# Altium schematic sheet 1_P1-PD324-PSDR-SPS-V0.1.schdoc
size 848 x 601 mm; Symbol: Drawing-Symbol_A4; Device: Drawing-Symbol_A4; Company: 嘉立创EDA; Version: V1.0; Page Size: A4; @Project Name: PD324; @Page Count: 2; @Update Date: 2025-04-30; @Create Date: 2025-04-12; @Schematic Name: Schematic1; @Page No: 1; @Page Name: P1-PD324-PSDR-SPS-V0.1; @Create Time: 09:33:54; @Update Time: 09:23:29; Width: 3304; Height: 2338; Region Start: 1; X Region Count: 6; Y Region Count: 4; Blade Width: 10; Title Block Position: 3; @Board Name: Board1
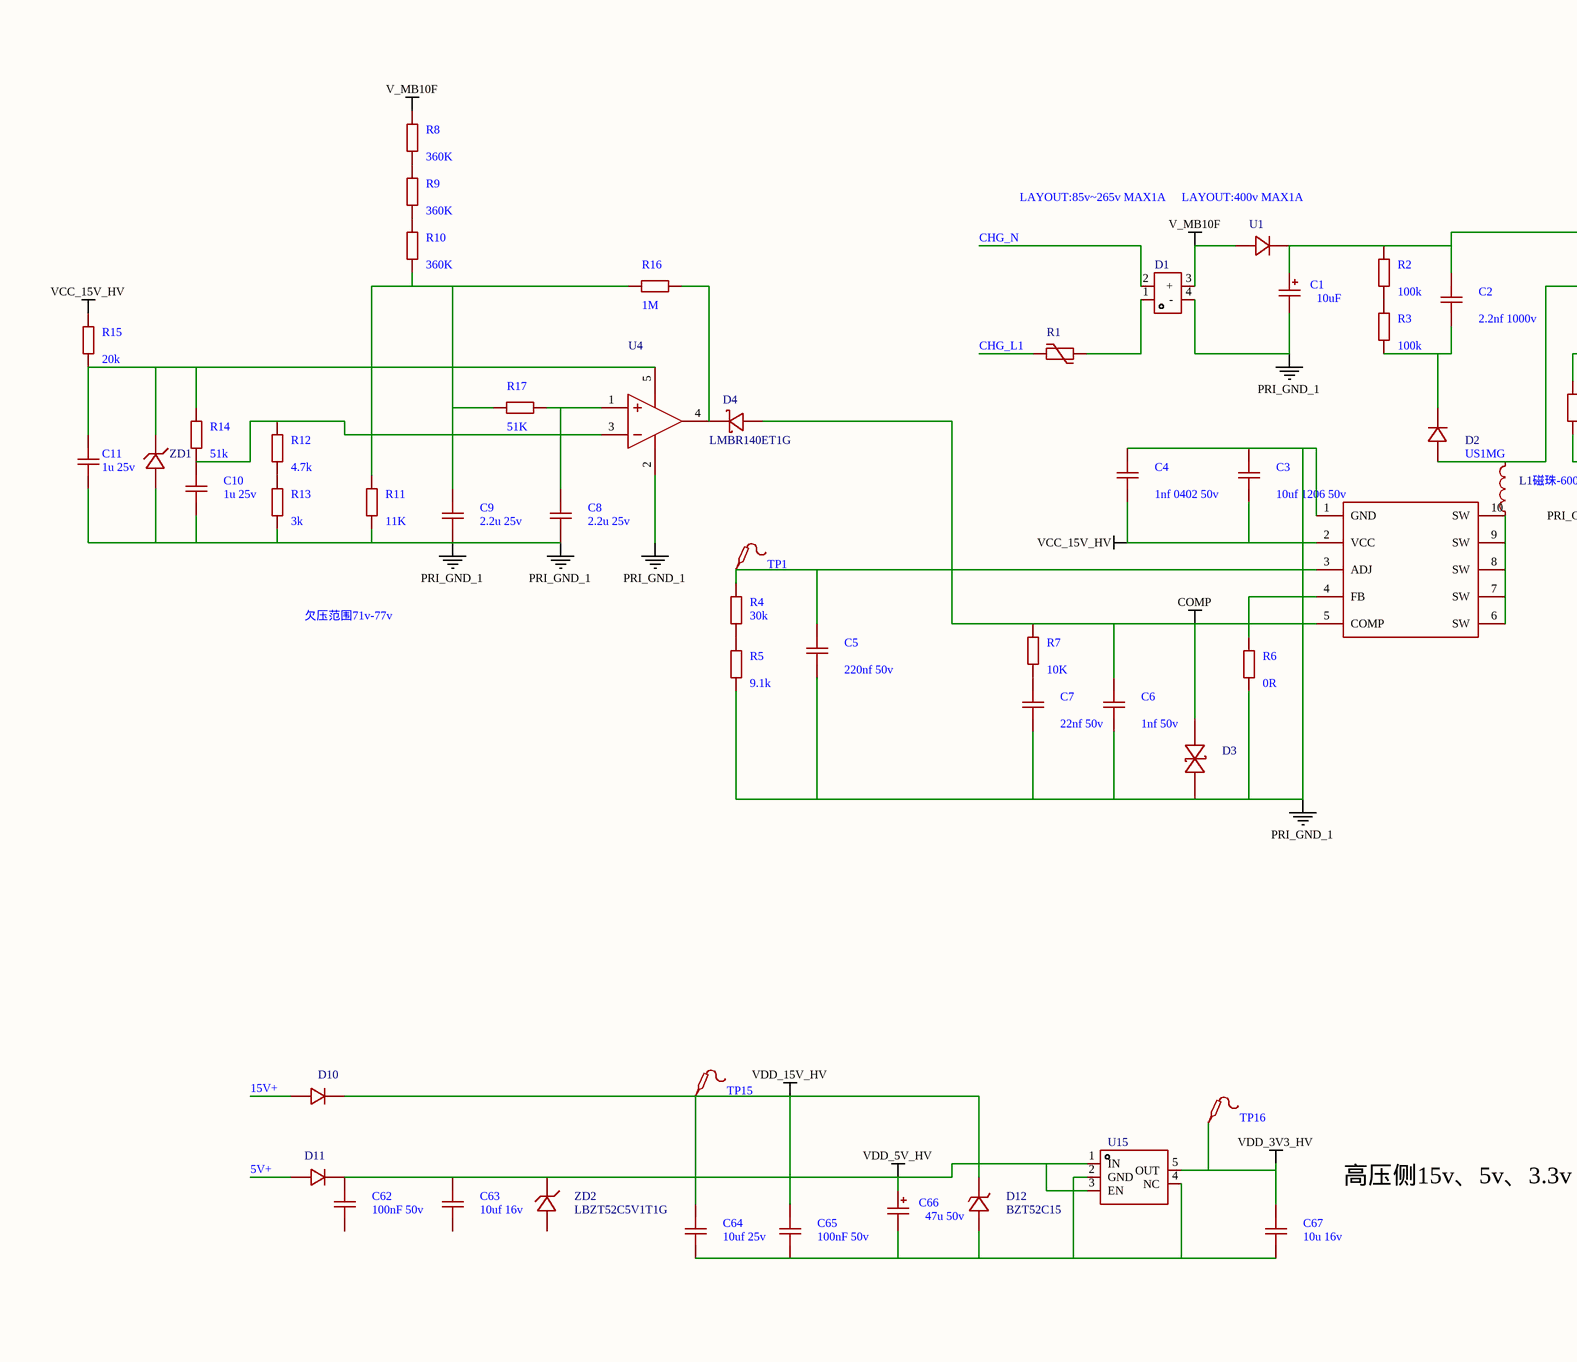
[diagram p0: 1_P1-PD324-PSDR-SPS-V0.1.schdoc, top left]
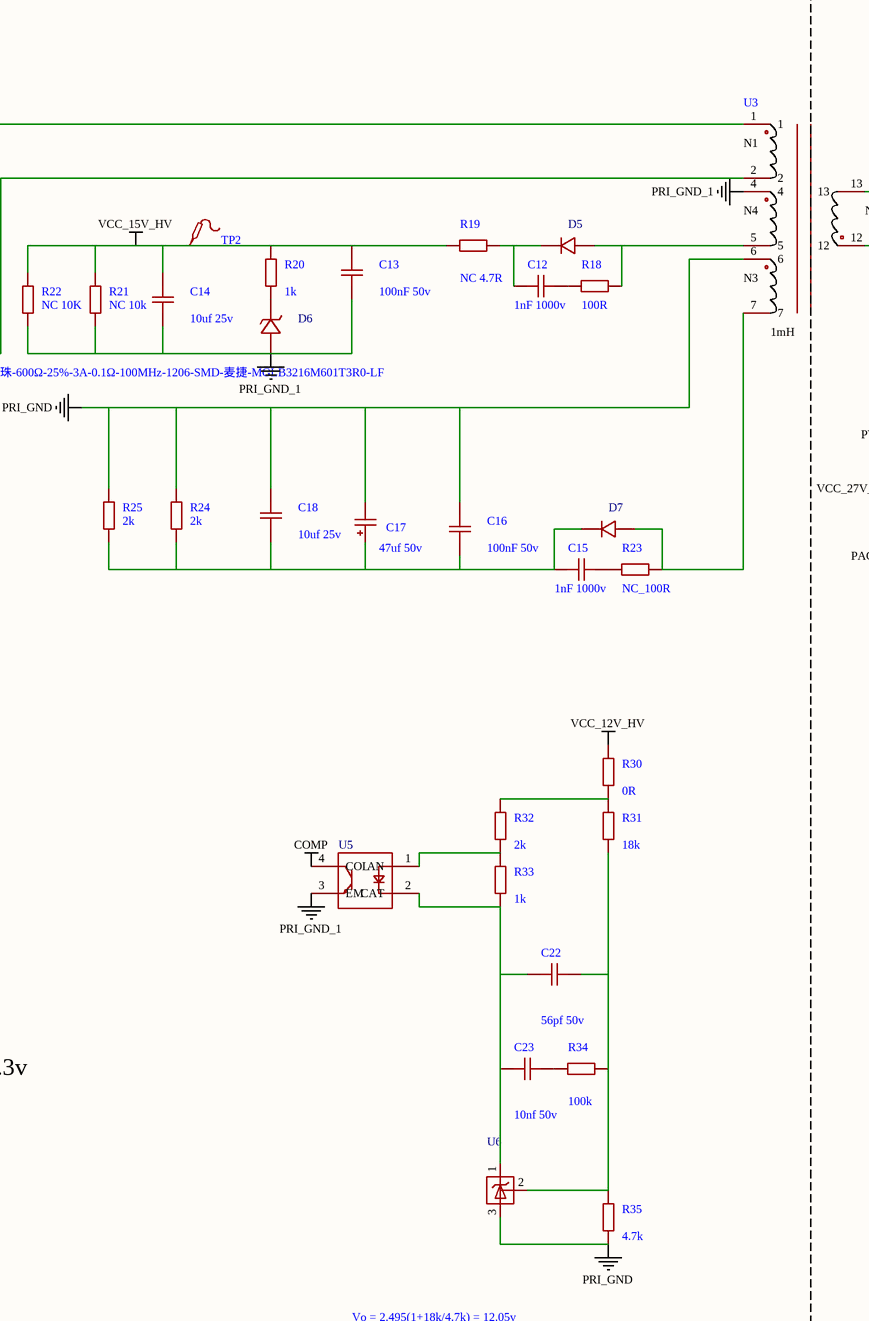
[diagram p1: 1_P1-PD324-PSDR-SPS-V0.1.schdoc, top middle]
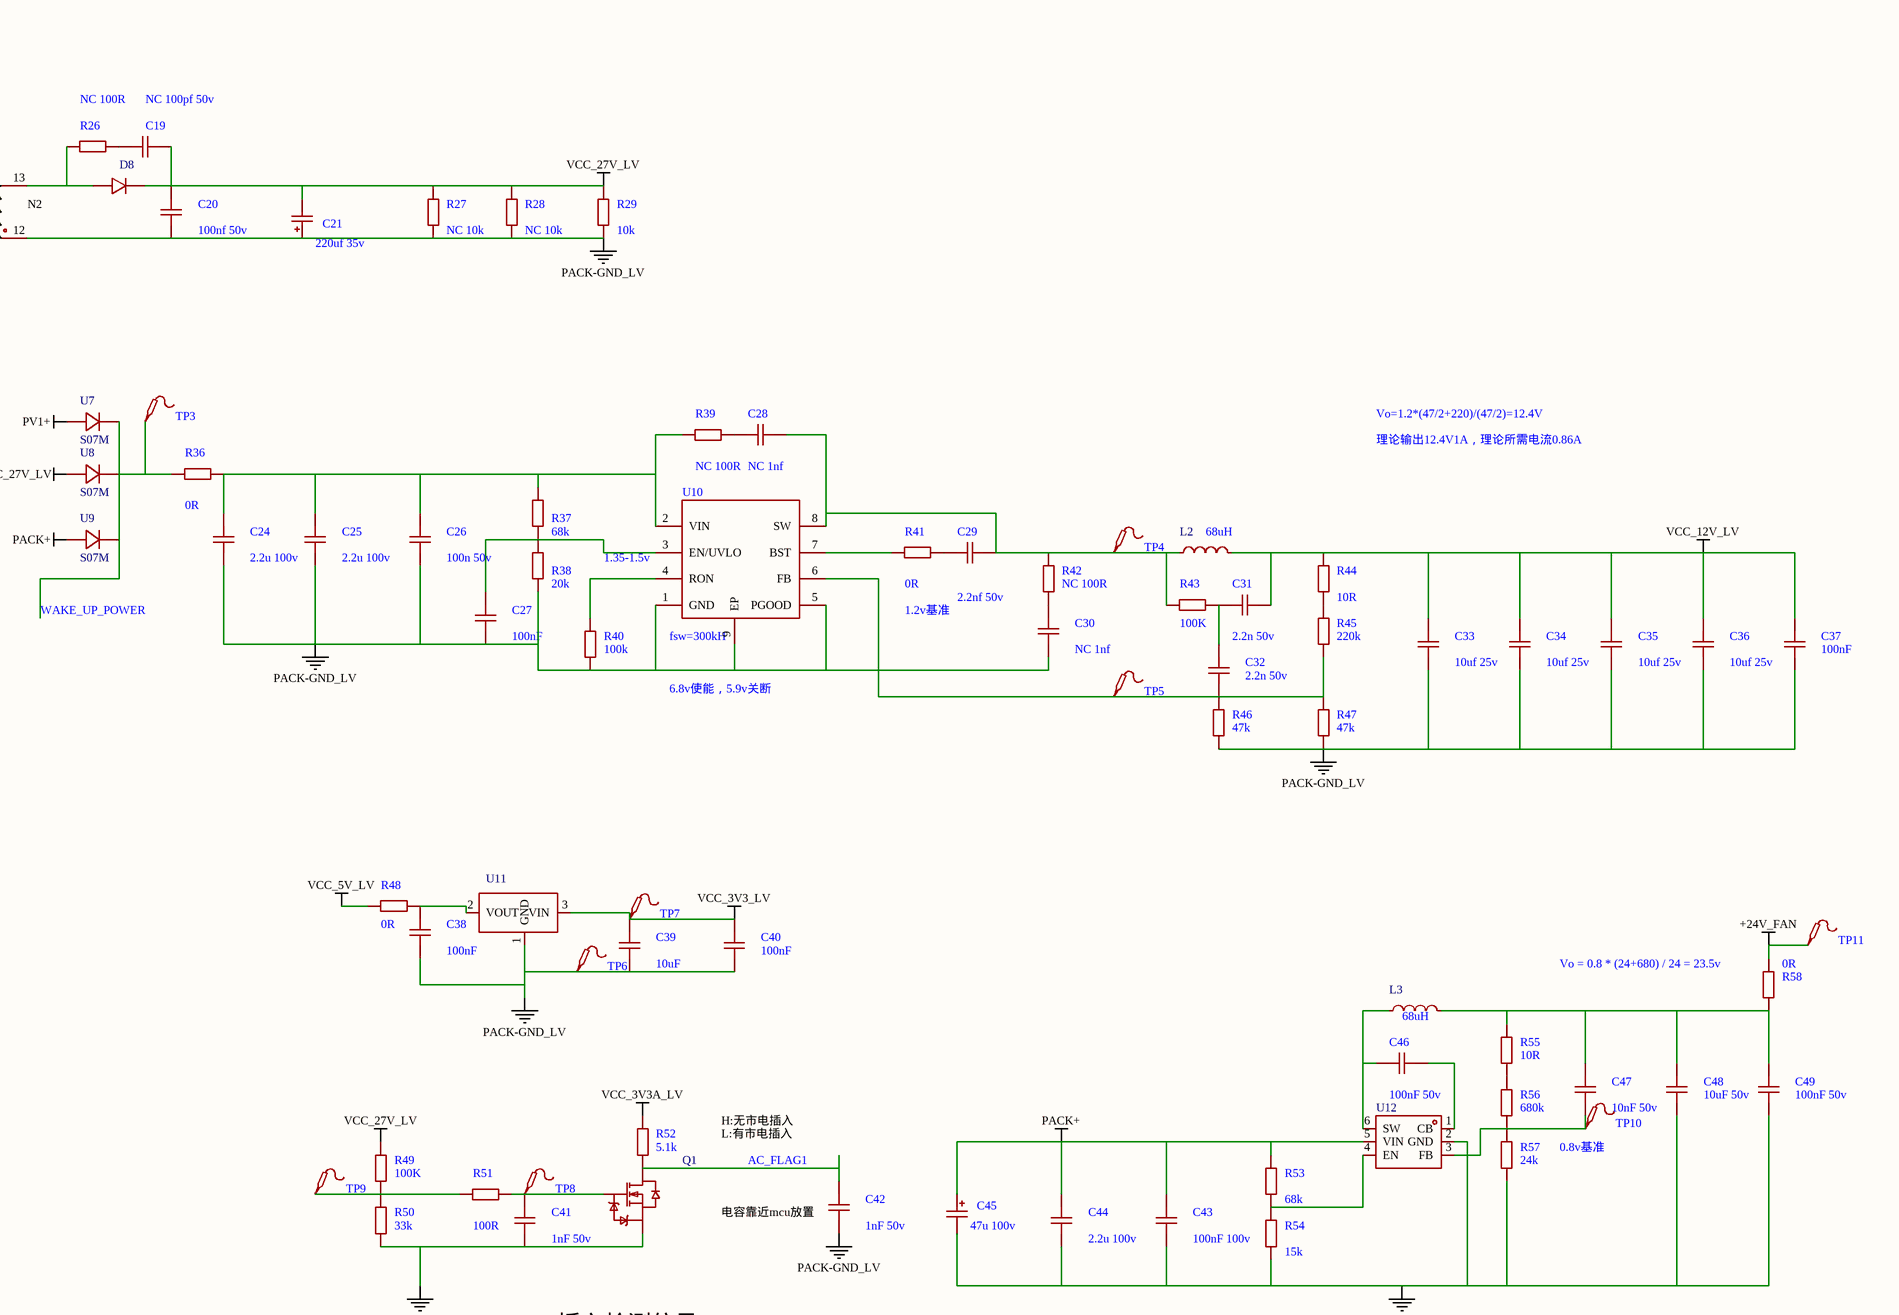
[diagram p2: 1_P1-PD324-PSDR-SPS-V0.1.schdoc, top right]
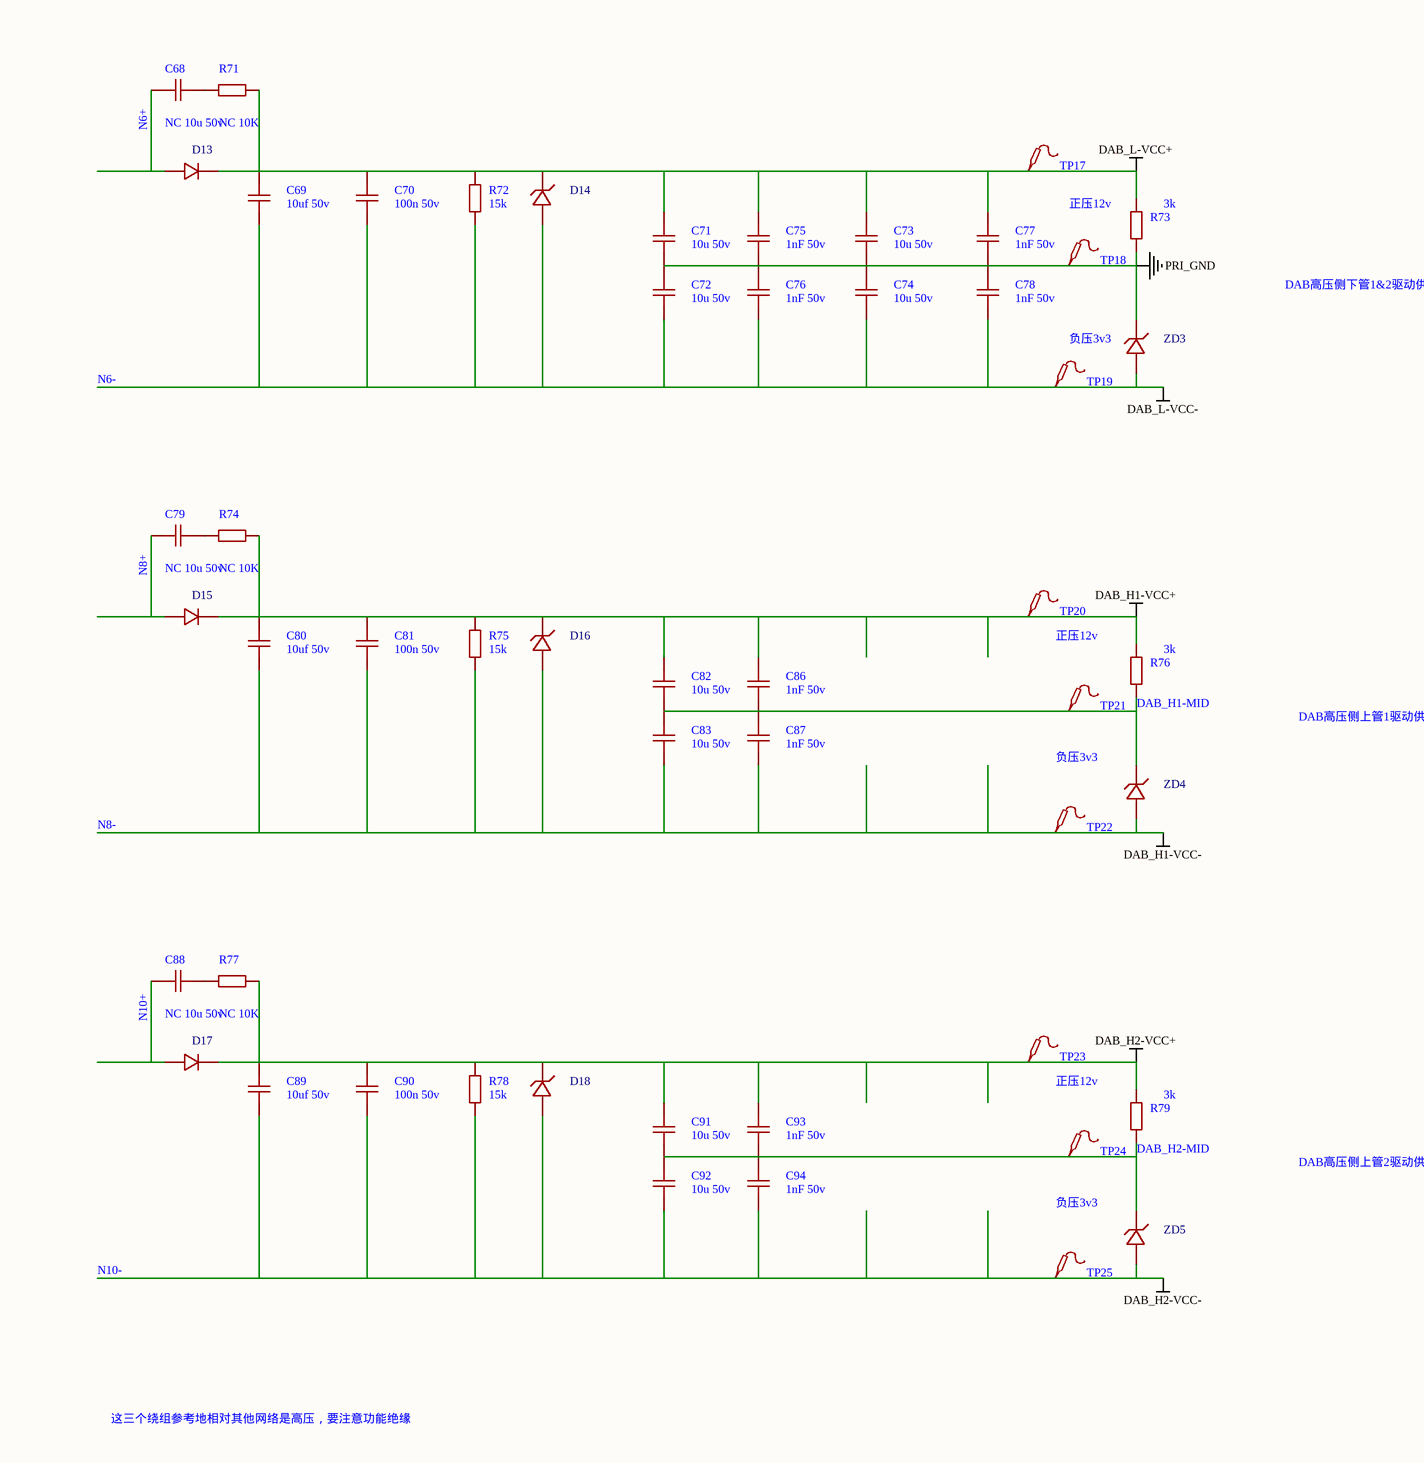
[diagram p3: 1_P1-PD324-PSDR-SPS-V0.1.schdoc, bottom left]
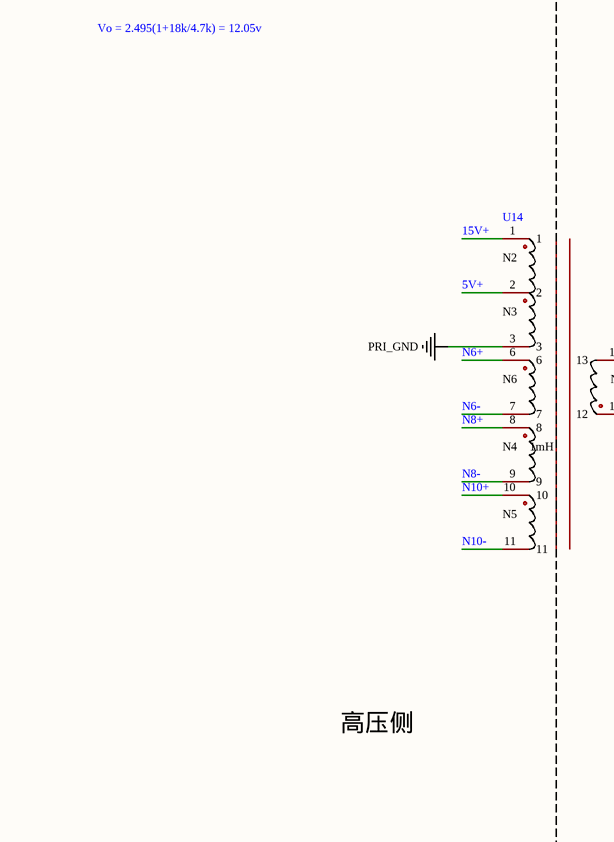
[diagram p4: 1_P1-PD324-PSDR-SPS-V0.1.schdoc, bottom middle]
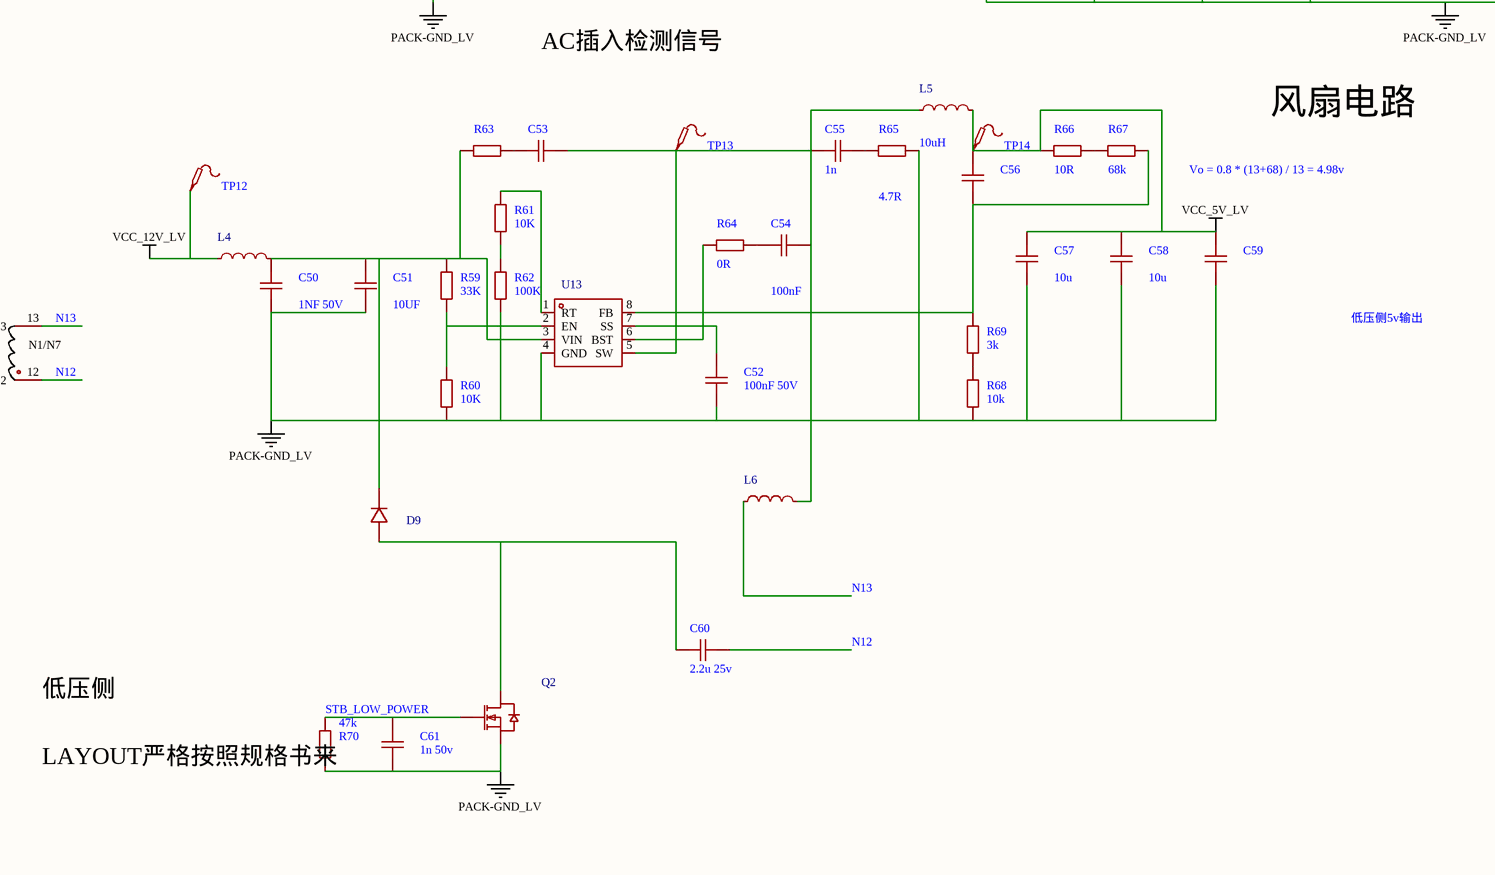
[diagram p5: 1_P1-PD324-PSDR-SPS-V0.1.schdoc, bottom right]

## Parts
C1  10uF  [C_Ele_SMD_3x5.4mm]
C2  2.2nf 1000v  [C1206]
C3  10uf 1206 50v  [C1206]
C4  1nf 0402 50v  [C1206]
C5  220nf 50v  [C0603]
C6  1nf 50v  [C0402]
C7  22nf 50v  [C0603]
C8  2.2u 25v  [C0805]
C9  2.2u 25v  [C0805]
C10  1u 25v  [C0805]
C11  1u 25v  [C0805]
C12  1nF 1000v  [C1206]
C13  100nF 50v  [C0603]
C14  10uf 25v  [C1206]
C15  1nF 1000v  [C1206]
C16  100nF 50v  [C0603]
C17  47uf 50v  [C_Ele_SMD_3x5.4mm]
C18  10uf 25v  [C1206]
C19  NC 100pf 50v  [C0603]
C20  100nf 50v  [C0603]
C21  220uf 35v  [C_Ele_SMD_3x5.4mm]
C22  56pf 50v  [C0402]
C23  10nf 50v  [C0402]
C24  2.2u 100v  [C1206]
C25  2.2u 100v  [C1206]
C26  100n 50v  [C1206]
C27  100nF  [C0603]
C28  NC 1nf  [C1206]
C29  2.2nf 50v  [C0402]
C30  NC 1nf  [C0402]
C31  2.2n 50v  [C0402]
C32  2.2n 50v  [C0402]
C33  10uf 25v  [C1206]
C34  10uf 25v  [C1206]
C35  10uf 25v  [C1206]
C36  10uf 25v  [C1206]
C37  100nF  [C0603]
C38  100nF  [C0603]
C39  10uF  [C0603]
C40  100nF  [C0402]
C41  1nF 50v  [C0402]
C42  1nF 50v  [C0402]
C43  100nF 100v  [C1206]
C44  2.2u 100v  [C1206]
C45  47u 100v  [C_Ele_SMD_3x5.4mm]
C46  100nF 50v  [C0603]
C47  10nF 50v  [C0402]
C48  10uF 50v  [C1206]
C49  100nF 50v  [C0603]
C50  1NF 50V  [C0402]
C51  10UF  [C1206]
C52  100nF 50V  [C0603]
C53  1nF 50V  [C0402]  (value not drawn)
C54  100nF  [C0603]
C55  1n  [C0402]
C56  NC 12p  [C0402]  (value not drawn)
C57  10u  [C1206]
C58  10u  [C1206]
C59  100nF  [C0402]  (value not drawn)
C60  2.2u 25v  [C0805]
C61  1n 50v  [C0402]
C62  100nF 50v  [C0603]
C63  10uf 16v  [C0805]
C64  10uf 25v  [C1206]
C65  100nF 50v  [C0603]
C66  47u 50v  [C_Ele_SMD_3x5.4mm]
C67  10u 16v  [C0805]
C68  NC 10u 50v  [C1206]
C69  10uf 50v  [C1206]
C70  100n 50v  [C0603]
C71  10u 50v  [C1206]
C72  10u 50v  [C1206]
C73  10u 50v  [C1206]
C74  10u 50v  [C1206]
C75  1nF 50v  [C0603]
C76  1nF 50v  [C0603]
C77  1nF 50v  [C0603]
C78  1nF 50v  [C0603]
C79  NC 10u 50v  [C1206]
C80  10uf 50v  [C1206]
C81  100n 50v  [C0603]
C82  10u 50v  [C1206]
C83  10u 50v  [C1206]
C86  1nF 50v  [C0603]
C87  1nF 50v  [C0603]
C88  NC 10u 50v  [C1206]
C89  10uf 50v  [C1206]
C90  100n 50v  [C0603]
C91  10u 50v  [C1206]
C92  10u 50v  [C1206]
C93  1nF 50v  [C0603]
C94  1nF 50v  [C0603]
D1  MB10F  [MBF_L4.8-W3.9-P2.50-LS6.7-TL]  (value not drawn)
D2  US1MG  [SMA_L4.3-W2.6-LS5.2-RD]
D3  SMAJ36CA  [SMA_L4.4-W2.8-LS5.1-BI]  (value not drawn)
D4  LMBR140ET1G  [SOD-323HE_L2.0-W1.4-LS2.5-RD]
D5  SODSF14-SH  [SOD-123FL_L2.8-W1.8-LS3.7-RD-1]  (value not drawn)
D6  BZT52C15  [SOD-123_L2.7-W1.7-LS3.8-RD]  (value not drawn)
D7  SODSF14-SH  [SOD-123FL_L2.8-W1.8-LS3.7-RD-1]  (value not drawn)
D8  SODSF14-SH  [SOD-123FL_L2.8-W1.8-LS3.7-RD-1]  (value not drawn)
D9  SODSF14-SH  [SOD-123FL_L2.8-W1.8-LS3.7-RD-1]  (value not drawn)
D10  ES07D  [SOD-123FL_L2.7-W1.8-LS3.8-RD]  (value not drawn)
D11  ES07D  [SOD-123FL_L2.7-W1.8-LS3.8-RD]  (value not drawn)
D12  BZT52C15  [SOD-123_L2.7-W1.7-LS3.8-RD]
D13  ES07D  [SOD-123FL_L2.7-W1.8-LS3.8-RD]  (value not drawn)
D14  LM3Z18VT1G  [SOD-323_L1.8-W1.3-LS2.5-RD]  (value not drawn)
D15  ES07D  [SOD-123FL_L2.7-W1.8-LS3.8-RD]  (value not drawn)
D16  LM3Z18VT1G  [SOD-323_L1.8-W1.3-LS2.5-RD]  (value not drawn)
D17  ES07D  [SOD-123FL_L2.7-W1.8-LS3.8-RD]  (value not drawn)
D18  LM3Z18VT1G  [SOD-323_L1.8-W1.3-LS2.5-RD]  (value not drawn)
L1  磁珠-600Ω-25%-3A-0.1Ω-100MHz-1206-SMD-麦捷-MGLB3216M601T3R0-LF  [L1206]
L2  68uH  [L0603]
L3  68uH  [L0603]
L4  磁珠-600Ω-25%-3A-0.1Ω-100MHz-1206-SMD-麦捷-MGLB3216M601T3R0-LF  [L1206]  (value not drawn)
L5  10uH  [L1206]
L6  磁珠-100MHz-120Ω-25%-3A-0.06Ω-SMD-麦捷-MGLB1608M121T3R0-LF  [L0603]  (value not drawn)
Q1  L2N7002SLT1G  [SOT-23_L2.9-W1.3-P1.90-LS2.4-BR]  (value not drawn)
Q2  YJL3400A  [SOT-23-3_L2.9-W1.3-P1.90-LS2.4-BR]  (value not drawn)
R1  MF0903003M4BP0FPT0  [RES-TH_L11.0-W6.0-P5.00-D0.7-S6.40]  (value not drawn)
R2  100k  [R1206]
R3  100k  [R1206]
R4  30k  [R0603]
R5  9.1k  [R0603]
R6  0R  [R0603]
R7  10K  [R0603]
R8  360K  [R1206]
R9  360K  [R1206]
R10  360K  [R1206]
R11  11K  [R0603]
R12  4.7k  [R0603]
R13  3k  [R0603]
R14  51k  [R0603]
R15  20k  [R0603]
R16  1M  [R0603]
R17  51K  [R0603]
R18  100R  [R1206]
R19  NC 4.7R  [R1206]
R20  1k  [R0603]
R21  NC 10k  [R1206]
R22  NC 10K  [R1206]
R23  NC_100R  [R1206]
R24  2k  [R1206]
R25  2k  [R1206]
R26  NC 100R  [R1206]
R27  NC 10k  [R1206]
R28  NC 10k  [R1206]
R29  10k  [R1206]
R30  0R  [R0603]
R31  18k  [R0603]
R32  2k  [R0603]
R33  1k  [R0603]
R34  100k  [R0603]
R35  4.7k  [R0603]
R36  0R  [R1206]
R37  68k  [R0603]
R38  20k  [R0603]
R39  NC 100R  [R1206]
R40  100k  [R0603]
R41  0R  [R0603]
R42  NC 100R  [R1206]
R43  100K  [R0603]
R44  10R  [R0603]
R45  220k  [R0402]
R46  47k  [R0603]
R47  47k  [R0603]
R48  0R  [R1206]
R49  100K  [R0603]
R50  33k  [R0603]
R51  100R  [R0603]
R52  5.1k  [R0402]
R53  68k  [R0603]
R54  15k  [R0603]
R55  10R  [R0603]
R56  680k  [R0603]
R57  24k  [R0603]
R58  0R  [R1206]
R59  33K  [R0603]
R60  10K  [R0603]
R61  10K  [R0603]
R62  100K  [R0603]
R63  10K  [R1206]  (value not drawn)
R64  0R  [R0603]
R65  4.7R  [R1206]
R66  10R  [R0603]
R67  68k  [R0603]
R68  10k  [R0603]
R69  3k  [R0603]
R70  47k  [R0603]
R71  NC 10K  [R1206]
R72  15k  [R0603]
R73  3k  [R1206]
R74  NC 10K  [R1206]
R75  15k  [R0603]
R76  3k  [R1206]
R77  NC 10K  [R1206]
R78  15k  [R0603]
R79  3k  [R1206]
TP1  (no value)  [Test-Point-0.5mm]
TP2  (no value)  [Test-Point-0.5mm]
TP3  (no value)  [Test-Point-0.5mm]
TP4  (no value)  [Test-Point-0.5mm]
TP5  (no value)  [Test-Point-0.5mm]
TP6  (no value)  [Test-Point-0.5mm]
TP7  (no value)  [Test-Point-0.5mm]
TP8  (no value)  [Test-Point-0.5mm]
TP9  (no value)  [Test-Point-0.5mm]
TP10  (no value)  [Test-Point-0.5mm]
TP11  (no value)  [Test-Point-0.5mm]
TP12  (no value)  [Test-Point-0.5mm]
TP13  (no value)  [Test-Point-0.5mm]
TP14  (no value)  [Test-Point-0.5mm]
TP15  (no value)  [Test-Point-0.5mm]
TP16  (no value)  [Test-Point-0.5mm]
TP17  (no value)  [Test-Point-0.5mm]
TP18  (no value)  [Test-Point-0.5mm]
TP19  (no value)  [Test-Point-0.5mm]
TP20  (no value)  [Test-Point-0.5mm]
TP21  (no value)  [Test-Point-0.5mm]
TP22  (no value)  [Test-Point-0.5mm]
TP23  (no value)  [Test-Point-0.5mm]
TP24  (no value)  [Test-Point-0.5mm]
TP25  (no value)  [Test-Point-0.5mm]
U1  S07M  [SOD-123FL_L2.8-W1.8-LS3.7-RD]  (value not drawn)
U2  (no value)
U3  (no value)
U4  LM321LVIDBVR  [SOT-23-5_L3.0-W1.7-P0.95-LS2.8-BL]  (value not drawn)
U5  EL1019(TA)-VG  [SOP-4_L7.5-W3.8-P2.54-LS10.2-TL]  (value not drawn)
U6  TL431NSG-AE2-R  [SOT-23-3_L2.9-W1.3-P1.90-LS2.4-BR]  (value not drawn)
U7  S07M  [SOD-123FL_L2.8-W1.8-LS3.7-RD]
U8  S07M  [SOD-123FL_L2.8-W1.8-LS3.7-RD]
U9  S07M  [SOD-123FL_L2.8-W1.8-LS3.7-RD]
U10  (no value)
U11  SGM2212-3.3XOB2G/TR  [TO-252-2_L6.6-W6.1-P4.57-LS10.1-BR-CW]  (value not drawn)
U12  LMR51610XDBVR  [SOT-23-6_L2.9-W1.6-P0.95-LS2.8-BR]  (value not drawn)
U13  TPS62933FDRLR  [SOT-583-8_L2.1-W1.2-P0.50-LS1.6-BR]  (value not drawn)
U14  (no value)
U15  TLV74033PDBVR  [SOT-23-5_L2.9-W1.6-P0.95-LS2.8-BL]  (value not drawn)
ZD1  LBZT52C5V1T1G  [SOD-123_L2.8-W1.8-LS3.7-RD]  (value not drawn)
ZD2  LBZT52C5V1T1G  [SOD-123_L2.8-W1.8-LS3.7-RD]
ZD3  LBZT52C3V3T1G  [SOD-123_L2.8-W1.8-LS3.7-RD]  (value not drawn)
ZD4  LBZT52C3V3T1G  [SOD-123_L2.8-W1.8-LS3.7-RD]  (value not drawn)
ZD5  LBZT52C3V3T1G  [SOD-123_L2.8-W1.8-LS3.7-RD]  (value not drawn)

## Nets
+24V_FAN: R58.2 TP11.1
COMP: C6.2 D3.2 D4.2 R7.2 U2.5(COMP) U5.4(COL)
DAB_H1-VCC+: C80.2 C81.2 C82.2 C86.2 D15.1(C) D16.1(K) R74.2 R75.2 R76.2 TP20.1
DAB_H2-VCC+: C89.2 C90.2 C91.2 C93.2 D17.1(C) D18.1(K) R77.2 R78.2 R79.2 TP23.1
DAB_L-VCC+: C69.2 C70.2 C71.2 C73.2 C75.2 C77.2 D13.1(C) D14.1(K) R71.2 R72.2 R73.2 TP17.1
N6-: C69.1 C70.1 C72.1 C74.1 C76.1 C78.1 D14.2(A) R72.1 TP19.1 U14.7 ZD3.2(A)  [also labelled DAB_L-VCC-]
N8-: C80.1 C81.1 C83.1 C87.1 D16.2(A) R75.1 TP22.1 U14.9 ZD4.2(A)  [also labelled DAB_H1-VCC-]
N10-: C89.1 C90.1 C92.1 C94.1 D18.2(A) R78.1 TP25.1 U14.11 ZD5.2(A)  [also labelled DAB_H2-VCC-]
PACK+: C43.2 C44.2 C45.1 R53.2 U9.2(A) U12.5(VIN)
PACK-GND_LV: C20.1 C21.1 C24.1 C25.1 C26.1 C27.1 C30.1 C33.1 C34.1 C35.1 C36.1 C37.1 C38.1 C39.1 C40.1 C41.1 C42.1 C43.1 C44.1 C45.2 C48.1 C49.1 C50.1 C51.1 C52.1 C57.1 C58.1 C59.1 C61.1 Q1.2(S) Q2.2(S) R27.1 R28.1 R29.1 R38.1 R40.1 R46.1 R47.1 R50.1 R54.1 R57.1 R60.1 R62.1 R65.2 R68.1 R70.1 TP6.1 U3.12 U10.1(GND) U10.5(PGOOD) U10.9(EP) U11.1(GND) U12.2(GND) U13.4(GND)
PRI_GND: C16.2 C17.2 C18.2 C71.1 C72.2 C73.1 C74.2 C75.1 C76.2 C77.1 C78.2 R24.2 R25.2 R35.2 R73.1 TP18.1 U3.6 U6.3(A) U14.3 ZD3.1(K)
PRI_GND_1: C1.2 C3.2 C4.2 C5.1 C6.1 C7.1 C8.1 C9.1 C10.1 C11.1 C13.1 C14.1 D1.4(-) D3.1 D6.2(A) R5.1 R6.1 R11.1 R13.1 R21.1 R22.1 U2.1(GND) U3.4 U4.2(V-) U5.3(EM) ZD1.2(A)
PV1+: U7.2(A)
V_MB10F: D1.3(+) R8.2 U1.2(A)
VCC_3V3_LV: C39.2 C40.2 TP7.1 U11.3(VIN)
VCC_3V3A_LV: R52.2
VCC_5V_LV: C56.2 C57.2 C58.2 C59.2 L5.2 R48.1 R66.1 TP14.1
VCC_12V_HV: R30.2
VCC_12V_LV: C31.2 C33.2 C34.2 C35.2 C36.2 C37.2 L2.2 L4.1 R44.2 TP12.1
VCC_15V_HV: C3.1 C4.1 C13.2 C14.2 R15.2 R19.1 R20.2 R21.2 R22.2 TP2.1 U2.2(VCC)
VCC_27V_LV: C19.2 C20.2 C21.2 D8.1 R27.2 R28.2 R29.2 R49.2 U8.2(A)
VDD_3V3_HV: C67.2 TP16.1 U15.5(OUT)
VDD_5V_HV: C62.2 C63.2 C66.1 D11.1(C) U15.1(IN) U15.3(EN) ZD2.1(K)
VDD_15V_HV: C64.2 C65.2 D10.1(C) D12.1(K) TP15.1
5V+: D11.2(A) U14.2
15V+: D10.2(A) U14.1
AC_FLAG1: C42.2 Q1.3(D) R52.1
CHG_L1: R1.1
CHG_N: D1.2
DAB_H1-MID: C82.1 C83.2 C86.1 C87.2 R76.1 TP21.1 ZD4.1(K)
DAB_H2-MID: C91.1 C92.2 C93.1 C94.2 R79.1 TP24.1 ZD5.1(K)
N6+: C68.1 D13.2(A) U14.6
N8+: C79.1 D15.2(A) U14.8
N10+: C88.1 D17.2(A) U14.10
N12: C60.2 U14.12
N13: L6.1 U14.13
STB_LOW_POWER: C61.2 Q2.1(G) R70.2
WAKE_UP_POWER: R36.1 TP3.1 U7.1(K) U8.1(K) U9.1(K)
NetC1_1: C1.1 C2.2 R2.2 U1.1(K) U3.1
NetC2_1: C2.1 D2.1(C) R3.1
NetC5_2: C5.2 R4.2 TP1.1 U2.3(ADJ)
NetC7_2: C7.2 R7.1
NetC8_2: C8.2 R17.2 U4.1(+IN)
NetC9_2: C9.2 R10.1 R11.2 R16.1 R17.1
NetC10_2: C10.2 R12.2 R14.1 U4.3(-IN)
NetC11_2: C11.2 R14.2 R15.1 U4.5(V+) ZD1.1(K)
NetC12_1: C12.1 D5.1 R19.2
NetC12_2: C12.2 R18.1
NetC15_1: C15.1 C16.1 C17.1 C18.1 D7.1 R24.1 R25.1
NetC15_2: C15.2 R23.1
NetC19_1: C19.1 R26.2
NetC22_1: C22.1 C23.1 R33.1 U5.2(CAT) U6.1(K)
NetC22_2: C22.2 R31.1 R34.1 R35.1 U6.2(R)
NetC23_2: C23.2 R34.2
NetC24_2: C24.2 C25.2 C26.2 R36.2 R37.2 R39.1 U10.2(VIN)
NetC27_2: C27.2 R37.1 R38.2 U10.3(EN/UVLO)
NetC28_1: C28.1 R39.2
NetC28_2: C28.2 C29.2 L2.1 R42.2 R43.1 TP4.1 U10.8(SW)
NetC29_1: C29.1 R41.2
NetC30_2: C30.2 R42.1
NetC31_1: C31.1 C32.2 R43.2
NetC32_1: C32.1 R45.1 R46.2 R47.2 TP5.1 U10.6(FB)
NetC38_2: C38.2 R48.2 U11.2(VOUT)
NetC41_2: C41.2 Q1.1(G) R51.1 TP8.1
NetC46_1: C46.1 L3.1 U12.6(SW)
NetC46_2: C46.2 U12.1(CB)
NetC47_1: C47.1 R56.1 R57.2 TP10.1 U12.3(FB)
NetC47_2: C47.2 C48.2 C49.2 L3.2 R55.2 R58.1
NetC50_2: C50.2 C51.2 D9.1 L4.2 R59.2 R63.1 U13.3(VIN)
NetC52_2: C52.2 U13.7(SS)
NetC53_1: C53.1 R63.2
NetC53_2: C53.2 C54.2 C55.1 L5.1 L6.2 TP13.1 U13.5(SW)
NetC54_1: C54.1 R64.2
NetC55_2: C55.2 R65.1
NetC56_1: C56.1 R67.2 R69.2 U13.8(FB)
NetC60_1: C60.1 D9.2 Q2.3(D)
NetC64_1: C64.1 C65.1 C66.2 C67.1 D12.2(A) U15.2(GND) U15.4(NC)
NetC68_2: C68.2 R71.1
NetC79_2: C79.2 R74.1
NetC88_2: C88.2 R77.1
NetD1_1: D1.1 R1.2
NetD2_2: D2.2(A) L1.2 U3.2
NetD4_1: D4.1 R16.2 U4.4(OUT)
NetD5_2: D5.2 R18.2 U3.5
NetD6_1: D6.1(K) R20.1
NetD7_2: D7.2 R23.2 U3.7
NetD8_2: D8.2 R26.1 U3.13
NetL1_1: L1.1 U2.6(SW) U2.7(SW) U2.8(SW) U2.9(SW) U2.10(SW)
NetR2_1: R2.1 R3.2
NetR4_1: R4.1 R5.2
NetR6_2: R6.2 U2.4(FB)
NetR8_1: R8.1 R9.2
NetR9_1: R9.1 R10.2
NetR12_1: R12.1 R13.2
NetR30_1: R30.1 R31.2 R32.2
NetR32_1: R32.1 R33.2 U5.1(AN)
NetR40_2: R40.2 U10.4(RON)
NetR41_1: R41.1 U10.7(BST)
NetR44_1: R44.1 R45.2
NetR49_1: R49.1 R50.2 R51.2 TP9.1
NetR53_1: R53.1 R54.2 U12.4(EN)
NetR55_1: R55.1 R56.2
NetR59_1: R59.1 R60.2 U13.2(EN)
NetR61_1: R61.1 R62.2
NetR61_2: R61.2 U13.1(RT)
NetR64_1: R64.1 U13.6(BST)
NetR66_2: R66.2 R67.1
NetR68_2: R68.2 R69.1

Not connected (* = marked no-connect by the designer): C62 1; C63 1; ZD2 2(A)

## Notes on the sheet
- LAYOUT:85v|65v MAX1A
- (near U1) LAYOUT:400v MAX1A
- Vo=1.2*(47/2+220)/(47/2)=12.4V
- 理论输出12.4V1A，理论所需电流0.86A
- 欠压范围71v-77v
- (near U10) 1.35-1.5v
- 1.2v基准
- (near U10) fsw=300kH
- 6.8v使能，5.9v关断
- (near R58) Vo = 0.8 * (24+680) / 24 = 23.5v
- 高压侧15v、5v、3.3v
- H:无市电插入
- L:有市电插入
- (near TP10) 0.8v基准
- 电容靠近mcu放置
- Vo = 2.495(1+18k/4.7k) = 12.05v
- AC插入检测信号
- 风扇电路
- 正压12v
- Vo = 0.8 * (13+68) / 13 = 4.98v
- DAB高压侧下管1&2驱动供电
- 负压3v3
- 低压侧5v输出
- (near TP20) 正压12v
- DAB高压侧上管1驱动供电
- 高压侧
- 低压侧
- LAYOUT严格按照规格书来
- (near TP23) 正压12v
- DAB高压侧上管2驱动供电
- 这三个绕组参考地相对其他网络是高压，要注意功能绝缘

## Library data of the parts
C1 C17 C21 C45 C66 = C_Ele_SMD_3x5.4mm: Symbol: CAP; Add into BOM: yes
C2-C4 C12 C14 C15 C18 C24-C26 C28 C33-C36 C43 C44 C48 C51 C57 C58 C64 C68 C69 C71-C74 C79 C80 C82 C83 C88 C89 C91 C92 = CAP_1206: Symbol: CapAcitance; Convert to PCB: yes
C5 C7 C13 C16 C19 C20 C27 C37-C39 C46 C49 C52 C54 C62 C65 C70 C75-C78 C81 C86 C87 C90 C93 C94 = CAP_0603: Symbol: CapAcitance; Convert to PCB: yes
C6 C22 C23 C29-C32 C40-C42 C47 C50 C53 C55 C56 C59 C61 = CAP_0402: Symbol: CapAcitance; Convert to PCB: yes
C8-C11 C60 C63 C67 = CAP_0805: Symbol: CapAcitance; Convert to PCB: yes
D1 = MB10F: Manufacturer: JUXING(钜兴); Symbol: MB10F_C3011052; Add into BOM: yes; Forward Voltage (Vf@If): 1V; Reverse Voltage (Vr): 1kV; Average Rectified Current (Io): 800mA; Reverse Leakage Current (Ir): 5uA; Peak Forward Surge Current: 30A
D2 = US1MG: Manufacturer: SHIKUES(时科); Add into BOM: yes; Diode Configuration: 独立式; Forward Voltage (Vf@If): 1.65V@1A; Reverse Voltage (Vr): 1kV; Average Rectified Current (Io): 1A; Reverse Leakage Current: 5uA@1kV; Reverse Recovery Time (trr): 75ns
D3 = SMAJ36CA: Manufacturer: JJW(捷捷微); Symbol: SMAJ36CA_C356740; Add into BOM: yes; Reverse Stand-Off Voltage (Vrwm): 36V; Maximum Clamping Voltage: 58.1V; Peak Pulse Current (Ipp): 6.9A; Breakdown Voltage: 40V; Reverse Leakage Current (Ir): 1uA; Type: TVS
D4 = LMBR140ET1G: Manufacturer: LRC(乐山无线电); Add into BOM: yes; Voltage - Forward(Vf@If): 550mV; Voltage - DC Reverse(Vr): 40V; Current - Rectified: 1A; Reverse Leakage Current (Ir): 20uA
D5 D7-D9 = SODSF14-SH: Manufacturer: LRC(乐山无线电); Add into BOM: yes; Forward Voltage (Vf@If): 950mV; Reverse Voltage (Vr): 200V; Rectified Current: 1A; Reverse Leakage Current (Ir): 5uA
D6 D12 = BZT52C15: Manufacturer: TWGMC(台湾迪嘉); Symbol: BZT52C15_C727006; Add into BOM: yes; Diode Configuration: 独立式; Zener Voltage (Nom): 15V; Reverse Leakage Current (Ir): 100nA@10.5V; Zener Voltage (Range): 13.8V~15.6V; Power Dissipation: 500mW; Zener Impedance (Zzt): 30Ω
D10 D11 D13 D15 D17 = ES07D: Manufacturer: PINGWEI(平伟); Add into BOM: yes; Forward Voltage (Vf@If): 950mV@1A; Reverse Voltage (Vr): 200V; Rectified Current: 1A; Reverse Leakage Current (Ir): 5uA@200V; Reverse Recovery Time (trr): 35ns
D14 D16 D18 = LM3Z18VT1G: Manufacturer: LRC(乐山无线电); Add into BOM: yes; Diode Configuration: 独立式; Zener Voltage (Nom): 18V; Zener Voltage (Range): 16.8V~19.1V; Power Dissipation: 200mW; Zener Impedance (Zzt): 45Ω
L1 L4 L5 = L_1206: Symbol: CMI321609VR27KT; Add into BOM: yes
L2 L3 L6 = L_0603: Symbol: SDFL1608S100KTF; Add into BOM: yes
Q1 = L2N7002SLT1G: Manufacturer: LRC(乐山无线电); Add into BOM: yes; Type: 1个N沟道; Drain Source Voltage (Vdss): 60V; Continuous Drain Current (Id): 320mA; Power Dissipation (Pd): 300mW; Drain Source On Resistance (RDS(on)@Vgs,Id): 2.8Ω@10V,500mA; Gate Threshold Voltage (Vgs(th)@Id): 2V@250uA
Q2 = YJL3400A: Manufacturer: YANGJIE(扬杰); Add into BOM: yes; Type: 1个N沟道; Drain Source Voltage (Vdss): 30V; Continuous Drain Current (Id): 5.6A; Drain Source On Resistance (RDS(on)@Vgs,Id): 51mΩ@2.5V,3.0A; Power Dissipation (Pd): 1.2W; Gate Threshold Voltage (Vgs(th)@Id): 650mV@250uA; Total Gate Charge (Qg@Vgs): 4.8nC@4.5V; Input Capacitance (Ciss@Vds): 535pF@15V; Reverse Transfer Capacitance (Crss@Vds): 36pF@15V
R1 = MF0903003M4BP0FPT0: Manufacturer: STE(松田); Add into BOM: yes; Resistance @ 25℃: 3Ω; B Constant (25℃/50℃): 2600K; B Constant Tolerance: ±10%; Steady State Current (Max): 3A
R2 R3 R8-R10 R18 R19 R21-R29 R36 R39 R42 R48 R58 R63 R65 R71 R73 R74 R76 R77 R79 = Res_1206: Symbol: 电阻; Add into BOM: yes
R4-R7 R11-R17 R20 R30-R35 R37 R38 R40 R41 R43 R44 R46 R47 R49-R51 R53-R57 R59-R62 R64 R66-R70 R72 R75 R78 = Res_0603: Symbol: 电阻; Convert to PCB: yes
R45 R52 = Res_0402: Symbol: 电阻; Convert to PCB: yes
TP1-TP25 = Test-Point: Add into BOM: yes
U1 U7-U9 = S07M: Symbol: S07M_C2978864; Add into BOM: yes
U2 = PN8089HST-A1: Add into BOM: yes
U3 = 辅源反激交流电变压器1: Add into BOM: yes
U4 = LM321LVIDBVR: Manufacturer: TI(德州仪器); Add into BOM: yes; Number of Circuits: 单路; Gain Bandwidth Product(GBP): 1MHz; Slew Rate(SR): 1.5V/us; Current - Input Bias(Ib): 15pA; Output Current: 40mA
U5 = EL1019(TA)-VG: Manufacturer: EVERLIGHT(亿光); Add into BOM: yes; Input voltage type: DC; Output Type: 光电三极管; Voltage - Forward(Vf): 1.45V; Output Current: 50mA; Isolation Voltage(Vrms): 5kV; Reverse Voltage: 6V; Load Voltage: 80V; Number of Outputs: 1; Vce Saturation(VCE(sat)): 300mV@1mA,10mA; Rise time: 2us@5mA,100Ω; Fall time: 3us@5mA,100Ω
U6 = TL431NSG-AE2-R: Manufacturer: UTC(友顺); Add into BOM: yes
U10 = LM5164DDAR: Add into BOM: yes
U11 = SGM2212-3.3XOB2G/TR: Manufacturer: SGMICRO(圣邦微); Add into BOM: yes
U12 = LMR51610XDBVR: Manufacturer: TI(德州仪器); Add into BOM: yes; Function: 降压型; Output Type: 可调; Input Voltage: 4V~65V; Output Current: 1A; Switching Frequency: 400kHz~1.1MHz; Synchronous Rectification: 是; Number of Outputs: 1; Topology: 降压式; Quiescent Current (Iq): 420uA; Switch tube (built-in/external): 内置
U13 = TPS62933FDRLR: Manufacturer: TI(德州仪器); Add into BOM: yes; Function: 降压型; Output Type: 可调; Input Voltage: 3.8V~30V; Output Voltage: 800mV~22V; Output Current: 3A; Switching Frequency: 2.2MHz; Synchronous Rectification: 是; Number of Outputs: 1; Topology: 降压式; Switch tube (built-in/external): 内置
U14 = DAB功率管隔离供电变压器: Add into BOM: yes
U15 = TLV74033PDBVR: Add into BOM: yes
ZD1 ZD2 = LBZT52C5V1T1G: Manufacturer: LRC(乐山无线电); Add into BOM: yes; Diode Configuration: 独立式; Zener Voltage (Nom): 5.1V; Reverse Leakage Current (Ir): 2uA; Zener Voltage (Range): 4.8V~5.4V; Power Dissipation: 500mW; Zener Impedance (Zzt): 60Ω
ZD3-ZD5 = LBZT52C3V3T1G: Manufacturer: LRC(乐山无线电); Add into BOM: yes; Diode Configuration: 独立式; Zener Voltage (Nom): 3.3V; Reverse Leakage Current (Ir): 5uA; Zener Voltage (Range): 3.1V~3.5V; Power Dissipation: 500mW; Zener Impedance (Zzt): 95Ω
